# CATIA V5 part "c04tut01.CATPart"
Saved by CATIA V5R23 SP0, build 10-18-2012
Part number: c04tut01
Material "Copper": density 8900 kg/m3, Young's modulus 1.1e+11 Pa, Poisson ratio 0.33, thermal expansion 1.65e-05 1/K
Bounding box of the stored display mesh (mm): x -99.592 to 99.592, y -99.592 to 99.592, z 0 to 140
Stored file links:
  D:\APS\CATIA V5-6R-2013-Project\CATIA V5-6R2013_partfiles\Tutorials\c04_catia_v5-6r2013_tut\c04tut01.CATPart
  C:\Program Files\Dassault Systemes\B23\win_b64\startup\materials\Catalog.CATMaterial
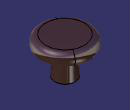
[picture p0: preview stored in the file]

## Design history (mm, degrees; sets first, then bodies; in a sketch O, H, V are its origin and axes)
Body1 (main body), material "Copper"
  Sketch1 on yz-plane, origin (0, 0, 0), H (0, 1, 0), V (0, 0, 1)
    axis line L1 (0, 92.904) -> (0, -81.406)
    point P1 (0, 92.904)
    line L2 (0, 0) -> (40, 0)
    line L3 (40, 0) -> (40, 70)
    line L4 (60, 90) -> (75, 90)
    arc A1 centre (75, 115) radius 25 from (75, 90) to (75, 140) ccw
    line L5 (75, 140) -> (0, 140)
    point P7 (0, 140)
    line L6 (0, 140) -> (0, 0)
    arc A2 centre (60, 70) radius 20 from (40, 70) to (60, 90) cw
    radius A2 = 20
    radius about axis L3 L1 = 40
    radius about axis L1 A1 = 100
    radius A1 = 25
    distance L2 L5 = 140
    coincidence: P1 V, P7 V
    vertical: L1 V, L3 V, L6 V
    horizontal: L2 H, L4 H
    tangency: A1 L4, L5 A1, A2 L3, A2 L4
  Shaft1: profile Sketch1, axis Sketch1.L1, angle 360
